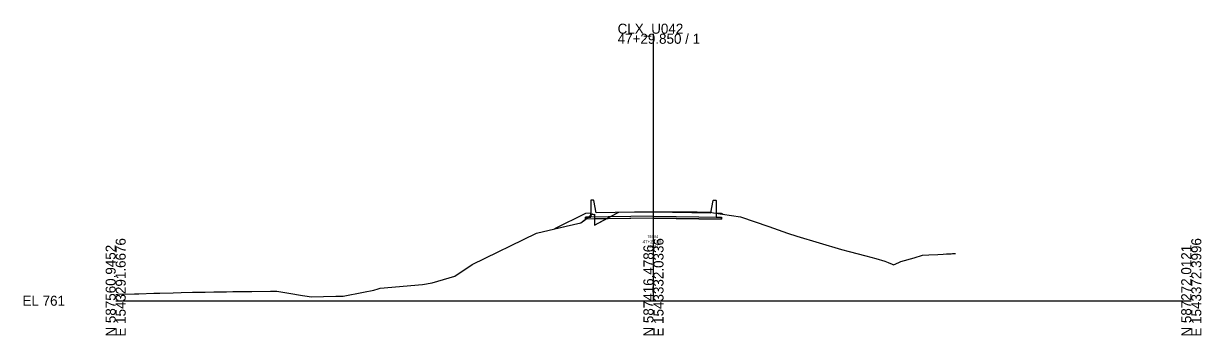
# Model space of a CAD drawing. Extents: x -26 to 1603, y -10 to 5557.
# Drawn here: x -25.7 to 302.8, y 2990.3 to 3077.4 of the extents above; entities that cross this region are included whole.
import ezdxf

# ---------------------------------------------------------------- set-up
doc = ezdxf.new("R2010")
doc.units = 0
for name, color, linetype in [('BR_P_Gen_Approach_Slab', 7, 'Continuous'), ('GK_Cells', 7, 'Continuous'), ('XS_P_Annotation', 7, 'Continuous'), ('XS_P_Earthwork_Shapes', 7, 'Continuous'), ('XS_P_Finished_Grade', 7, 'Continuous'), ('XS_P_Pavt_Layers', 7, 'Continuous'), ('XS_P_Pavt_Surface', 7, 'Continuous'), ('XS_P_Subgrade', 7, 'Continuous'), ('XS_X_Ground_Line', 7, 'Continuous')]:
    doc.layers.add(name, color=color, linetype=linetype)

msp = doc.modelspace()

# ---------------------------------------------------------------- linework, layer by layer
at = {"layer": 'BR_P_Gen_Approach_Slab'}
for p, q in [((132.56, 3028.08), (132.5, 3028.02)), ((132.5, 3028.02), (132.5, 3023.31)), ((133.27, 3028.08), (132.56, 3028.08)), ((133.34, 3028.02), (133.27, 3028.08)), ((134, 3024.58), (133.34, 3028.02)), ((166, 3024.58), (166.66, 3028.02)), ((166.66, 3028.02), (166.73, 3028.08)), ((166.73, 3028.08), (167.44, 3028.08)), ((167.44, 3028.08), (167.5, 3028.02)), ((167.5, 3028.02), (167.5, 3023.31))]:
    msp.add_line(p, q, dxfattribs=at)
at = {"layer": 'GK_Cells'}
for p, q in [((150, 3000), (150, 3074.53)), ((0, 3000), (150, 3000)), ((150, 3000), (300, 3000))]:
    msp.add_line(p, q, dxfattribs=at)
at = {"layer": 'XS_P_Earthwork_Shapes'}
for points in [[(132.5, 3023.87), (132.5, 3024.46), (131, 3024.33), (122.4, 3020.03), (125.65, 3020.82), (129.75, 3021.71), (131.12, 3022.79), (131, 3022.79), (131, 3023.29), (131.77, 3023.3)], [(131.77, 3023.3), (132.5, 3023.87), (132.5, 3024.46), (131, 3024.33), (122.4, 3020.03), (125.65, 3020.82), (129.75, 3021.71), (131.12, 3022.79), (131, 3022.79), (131, 3023.29)], [(131.77, 3023.3), (132.5, 3023.87), (132.5, 3024.46), (131, 3024.33), (122.4, 3020.03), (125.65, 3020.82), (129.75, 3021.71), (131.12, 3022.79), (131, 3022.79), (131, 3023.29)], [(133.56, 3022.83), (131.12, 3022.79), (131.77, 3023.3), (132.5, 3023.31), (132.5, 3023.87), (132.98, 3024.25), (133.27, 3024.06), (133.55, 3024.13)], [(133.56, 3022.83), (131.12, 3022.79), (131.77, 3023.3), (132.5, 3023.31), (132.5, 3023.87), (132.98, 3024.25), (133.27, 3024.06), (133.55, 3024.13)], [(132.5, 3023.87), (132.98, 3024.25), (133.27, 3024.06), (133.55, 3024.13), (133.56, 3022.83), (131.12, 3022.79), (131.77, 3023.3), (132.5, 3023.31)], [(131.77, 3023.3), (132.5, 3023.87), (132.5, 3023.31)], [(131.77, 3023.3), (132.5, 3023.87), (132.5, 3023.31)], [(131.77, 3023.3), (132.5, 3023.87), (132.5, 3023.31)], [(136.84, 3022.88), (133.56, 3022.83), (133.56, 3021.14)], [(136.84, 3022.88), (133.56, 3022.83), (133.56, 3021.14)], [(133.56, 3022.83), (133.56, 3021.14), (136.84, 3022.88)], [(136.84, 3022.88), (139.96, 3024.54), (140.35, 3024.74), (150, 3024.84), (150.39, 3024.84), (162.19, 3024.77), (162.64, 3024.76), (165.8, 3024.73), (166.7, 3024.58), (167.5, 3024.46), (167.5, 3023.31), (169, 3023.29), (169, 3022.79), (150, 3023.09)], [(136.84, 3022.88), (139.96, 3024.54), (140.35, 3024.74), (150, 3024.84), (150.39, 3024.84), (162.19, 3024.77), (162.64, 3024.76), (165.8, 3024.73), (166.7, 3024.58), (167.5, 3024.46), (167.5, 3023.31), (169, 3023.29), (169, 3022.79), (150, 3023.09)], [(136.84, 3022.88), (139.96, 3024.54), (140.35, 3024.74), (150, 3024.84), (150.39, 3024.84), (162.19, 3024.77), (162.64, 3024.76), (165.8, 3024.73), (166.7, 3024.58), (167.5, 3024.46), (167.5, 3023.31), (169, 3023.29), (169, 3022.79), (150, 3023.09)], [(167.5, 3024.46), (169.34, 3024.16), (169, 3024.33)], [(167.5, 3024.46), (169.34, 3024.16), (169, 3024.33)], [(167.5, 3024.46), (169.34, 3024.16), (169, 3024.33)]]:
    msp.add_lwpolyline(points, close=True, dxfattribs=at)
at = {"layer": 'XS_P_Finished_Grade'}
for p, q in [((131, 3024.33), (122.4, 3020.03)), ((132.5, 3024.46), (131, 3024.33)), ((167.5, 3024.46), (169, 3024.33)), ((169, 3024.33), (169.34, 3024.16))]:
    msp.add_line(p, q, dxfattribs=at)
at = {"layer": 'XS_P_Pavt_Layers'}
for p, q in [((150.02, 3023.59), (131, 3023.29)), ((131, 3022.79), (131, 3023.29)), ((150.03, 3023.09), (131, 3022.79)), ((149.97, 3023.09), (169, 3022.79)), ((149.98, 3023.59), (169, 3023.29)), ((169, 3022.79), (169, 3023.29))]:
    msp.add_line(p, q, dxfattribs=at)
at = {"layer": 'XS_P_Pavt_Surface'}
for q in [(134, 3024.58), (166, 3024.58)]:
    msp.add_line((150, 3024.84), q, dxfattribs=at)
at = {"layer": 'XS_P_Subgrade'}
msp.add_lwpolyline([(167.5, 3024.46), (167.5, 3023.31), (169, 3023.29), (169, 3022.79), (150, 3023.09), (131, 3022.79), (131, 3023.29), (132.5, 3023.31), (132.5, 3024.46)], dxfattribs=at)
at = {"layer": 'XS_X_Ground_Line'}
msp.add_lwpolyline([(0, 3001.77), (0.6, 3001.79), (5.21, 3001.92), (6.43, 3001.95), (10.6, 3002.08), (12.3, 3002.12), (15.99, 3002.23), (18.23, 3002.28), (21.46, 3002.38), (22.13, 3002.39), (24.97, 3002.42), (27.42, 3002.47), (30.94, 3002.51), (32.7, 3002.54), (36.93, 3002.58), (37.96, 3002.6), (43.21, 3002.63), (44.97, 3002.64), (48.34, 3002.1), (52.11, 3001.49), (53.41, 3001.28), (54.55, 3001.1), (57.94, 3001.18), (61.37, 3001.23), (62.36, 3001.25), (63.41, 3001.26), (69.13, 3002.41), (72.01, 3002.98), (73.18, 3003.33), (73.78, 3003.52), (85.56, 3004.5), (88.23, 3004.96), (94.59, 3006.88), (99.46, 3010.09), (117.39, 3018.82), (125.65, 3020.82), (129.75, 3021.71), (132.98, 3024.25), (133.27, 3024.06), (133.55, 3024.13), (133.56, 3021.14), (139.96, 3024.54), (140.35, 3024.74), (150, 3024.84), (150.39, 3024.84), (162.19, 3024.77), (162.64, 3024.76), (165.8, 3024.73), (166.7, 3024.58), (174.23, 3023.38), (182.14, 3020.68), (187.4, 3018.89), (190.02, 3017.99), (202.43, 3014.32), (204.54, 3013.77), (209.21, 3012.54), (212.05, 3011.8), (214.5, 3011), (215.47, 3010.69), (216.54, 3010.18), (216.94, 3010), (218.44, 3010.68), (219.04, 3010.95), (222.73, 3012.02), (225.06, 3012.69), (226.79, 3012.78), (229.27, 3012.92), (230.76, 3013), (231.76, 3013.05), (232.48, 3013.09), (233.01, 3013.12), (233.43, 3013.14), (234.27, 3013.18)], dxfattribs=at)

# ---------------------------------------------------------------- texts
at = {"layer": 'GK_Cells'}
for s, p in [('CLX_U042', (140, 3074.53)), ('47+29.850 / 1', (140, 3071.73)), ('EL 761', (-26, 2998.6))]:
    msp.add_text(s, height=2.8, dxfattribs=at).set_placement(p)
for s, p in [('E 1543291.6676', (2.8, 2990)), ('E 1543332.0336', (152.8, 2990)), ('E 1543372.3996', (302.8, 2990)), ('N 587560.9452', (0, 2990)), ('N 587416.4786', (150, 2990)), ('N 587272.0121', (300, 2990))]:
    msp.add_text(s, height=2.8, rotation=90, dxfattribs=at).set_placement(p)
at = {"layer": 'XS_P_Annotation'}
for s, height, p in [('47+29.85', 0.9, (147, 3016.05)), ('785.84', 0.7, (148.31, 3017.55)), ('785.84', 0.7, (148.31, 3014.75))]:
    msp.add_text(s, height=height, dxfattribs=at).set_placement(p)

doc.saveas('drawing.dxf')
